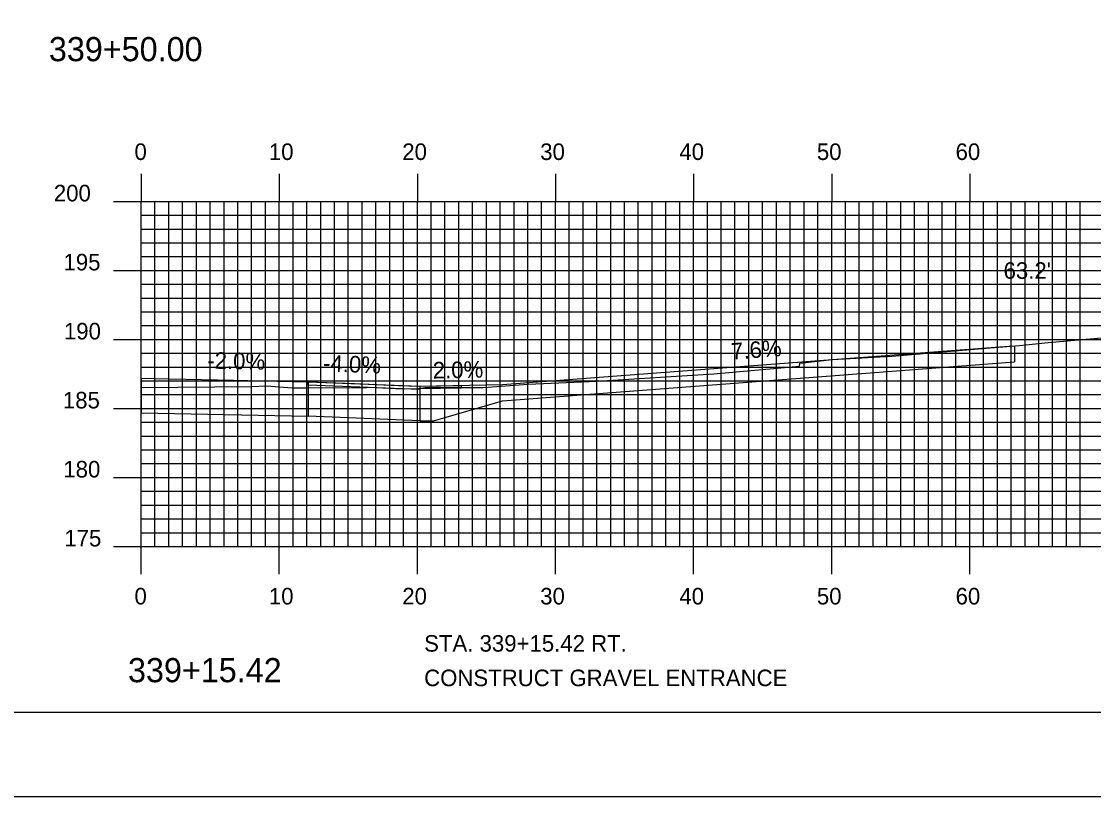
# Model space of a CAD drawing. Extents: x 1824360 to 1824703, y 442591 to 442811.
# Drawn here: x 1824516.7 to 1824594.3, y 442590.5 to 442646.7 of the extents above; entities that cross this region are included whole.
import ezdxf

# ---------------------------------------------------------------- set-up
doc = ezdxf.new("R2010")
doc.units = 0
for name, color, linetype in [('ANNOTATION', 7, 'Continuous'), ('BORDER', 7, 'Continuous'), ('D_Roadway_Centerline', 7, 'Continuous'), ('D_Roadway_Edge_Shoulder', 7, 'Continuous'), ('D_Roadway_FinishedGrade', 7, 'Continuous'), ('D_Text_Standard', 7, 'Continuous'), ('H_V ANNOTATION', 7, 'Continuous'), ('MAJOR', 7, 'Continuous'), ('MINOR', 7, 'Continuous'), ('PLOT BOUNDARY', 7, 'Continuous'), ('S_Roadway_Centerline', 7, 'Continuous')]:
    doc.layers.add(name, color=color, linetype=linetype)

msp = doc.modelspace()

# ---------------------------------------------------------------- linework, layer by layer
at = {"layer": 'ANNOTATION'}
for points in [[(1824545.506, 442620.277), (1824548.506, 442620.337), (1824548.506, 442620.17)], [(1824545.506, 442620.277), (1824545.506, 442620.11), (1824548.506, 442620.17)]]:
    msp.add_lwpolyline(points, dxfattribs=at)
at = {"layer": 'BORDER'}
msp.add_lwpolyline([(1824375.735, 442596.665), (1824695.735, 442596.665), (1824695.735, 442806.665), (1824375.735, 442806.665)], close=True, dxfattribs=at)
at = {"layer": 'D_Roadway_Centerline'}
msp.add_lwpolyline([(1824525.335, 442620.85), (1824525.335, 442620.85), (1824527.319, 442620.809), (1824528.58, 442620.783), (1824532.021, 442620.713), (1824536.27, 442620.626), (1824536.724, 442620.617), (1824537.438, 442620.602), (1824540.777, 442620.467), (1824543.959, 442620.339), (1824544.714, 442620.309), (1824545.506, 442620.277)], dxfattribs=at)
at = {"layer": 'D_Roadway_Edge_Shoulder'}
msp.add_lwpolyline([(1824537.438, 442620.602), (1824545.506, 442620.277), (1824545.506, 442620.027), (1824537.438, 442620.352)], close=True, dxfattribs=at)
msp.add_lwpolyline([(1824537.438, 442620.602), (1824545.506, 442620.277), (1824545.506, 442620.027), (1824537.438, 442620.352)], close=True, dxfattribs=at)
at = {"layer": 'D_Roadway_FinishedGrade'}
for p, q in [((1824588.582, 442623.208), (1824588.582, 442622.048)), ((1824537.438, 442620.602), (1824537.438, 442618.102)), ((1824545.506, 442620.277), (1824551.506, 442620.397)), ((1824546.506, 442617.777), (1824551.506, 442619.227)), ((1824545.506, 442617.777), (1824546.506, 442617.777))]:
    msp.add_line(p, q, dxfattribs=at)
for points in [[(1824551.506, 442620.397), (1824587.506, 442623.133), (1824588.582, 442623.208)], [(1824551.506, 442619.227), (1824588.582, 442622.044)], [(1824525.335, 442620.85), (1824525.335, 442618.35), (1824537.438, 442618.102)], [(1824545.506, 442620.277), (1824545.506, 442617.777), (1824537.438, 442618.102)]]:
    msp.add_lwpolyline(points, dxfattribs=at)
at = {"layer": 'MAJOR'}
for p, q in [((1824525.335, 442635.669), (1824525.335, 442633.665)), ((1824535.335, 442635.669), (1824535.335, 442633.665)), ((1824545.335, 442635.669), (1824545.335, 442633.665)), ((1824555.335, 442635.669), (1824555.335, 442633.665)), ((1824565.335, 442635.669), (1824565.335, 442633.665)), ((1824575.335, 442635.669), (1824575.335, 442633.665)), ((1824585.335, 442635.669), (1824585.335, 442633.665)), ((1824523.331, 442633.665), (1824525.335, 442633.665)), ((1824525.335, 442633.665), (1824665.335, 442633.665)), ((1824525.335, 442608.665), (1824525.335, 442633.665)), ((1824525.335, 442608.665), (1824525.335, 442633.665)), ((1824525.335, 442633.665), (1824665.335, 442633.665)), ((1824535.335, 442608.665), (1824535.335, 442633.665)), ((1824545.335, 442608.665), (1824545.335, 442633.665)), ((1824555.335, 442608.665), (1824555.335, 442633.665)), ((1824565.335, 442608.665), (1824565.335, 442633.665)), ((1824575.335, 442608.665), (1824575.335, 442633.665)), ((1824585.335, 442608.665), (1824585.335, 442633.665)), ((1824523.331, 442628.665), (1824525.335, 442628.665)), ((1824525.335, 442628.665), (1824665.335, 442628.665)), ((1824523.331, 442623.665), (1824525.335, 442623.665)), ((1824525.335, 442623.665), (1824665.335, 442623.665)), ((1824523.331, 442618.665), (1824525.335, 442618.665)), ((1824525.335, 442618.665), (1824665.335, 442618.665)), ((1824523.331, 442613.665), (1824525.335, 442613.665)), ((1824525.335, 442613.665), (1824665.335, 442613.665)), ((1824523.331, 442608.665), (1824525.335, 442608.665)), ((1824525.335, 442608.665), (1824665.335, 442608.665)), ((1824525.335, 442608.665), (1824665.335, 442608.665)), ((1824525.335, 442606.661), (1824525.335, 442608.665)), ((1824535.335, 442606.661), (1824535.335, 442608.665)), ((1824545.335, 442606.661), (1824545.335, 442608.665)), ((1824555.335, 442606.661), (1824555.335, 442608.665)), ((1824565.335, 442606.661), (1824565.335, 442608.665)), ((1824575.335, 442606.661), (1824575.335, 442608.665)), ((1824585.335, 442606.661), (1824585.335, 442608.665))]:
    msp.add_line(p, q, dxfattribs=at)
at = {"layer": 'MINOR'}
for p, q in [((1824526.335, 442608.665), (1824526.335, 442633.665)), ((1824527.335, 442608.665), (1824527.335, 442633.665)), ((1824528.335, 442608.665), (1824528.335, 442633.665)), ((1824529.335, 442608.665), (1824529.335, 442633.665)), ((1824530.335, 442608.665), (1824530.335, 442633.665)), ((1824531.335, 442608.665), (1824531.335, 442633.665)), ((1824532.335, 442608.665), (1824532.335, 442633.665)), ((1824533.335, 442608.665), (1824533.335, 442633.665)), ((1824534.335, 442608.665), (1824534.335, 442633.665)), ((1824536.335, 442608.665), (1824536.335, 442633.665)), ((1824537.335, 442608.665), (1824537.335, 442633.665)), ((1824538.335, 442608.665), (1824538.335, 442633.665)), ((1824539.335, 442608.665), (1824539.335, 442633.665)), ((1824540.335, 442608.665), (1824540.335, 442633.665)), ((1824541.335, 442608.665), (1824541.335, 442633.665)), ((1824542.335, 442608.665), (1824542.335, 442633.665)), ((1824543.335, 442608.665), (1824543.335, 442633.665)), ((1824544.335, 442608.665), (1824544.335, 442633.665)), ((1824546.335, 442608.665), (1824546.335, 442633.665)), ((1824547.335, 442608.665), (1824547.335, 442633.665)), ((1824548.335, 442608.665), (1824548.335, 442633.665)), ((1824549.335, 442608.665), (1824549.335, 442633.665)), ((1824550.335, 442608.665), (1824550.335, 442633.665)), ((1824551.335, 442608.665), (1824551.335, 442633.665)), ((1824552.335, 442608.665), (1824552.335, 442633.665)), ((1824553.335, 442608.665), (1824553.335, 442633.665)), ((1824554.335, 442608.665), (1824554.335, 442633.665)), ((1824556.335, 442608.665), (1824556.335, 442633.665)), ((1824557.335, 442608.665), (1824557.335, 442633.665)), ((1824558.335, 442608.665), (1824558.335, 442633.665)), ((1824559.335, 442608.665), (1824559.335, 442633.665)), ((1824560.335, 442608.665), (1824560.335, 442633.665)), ((1824561.335, 442608.665), (1824561.335, 442633.665)), ((1824562.335, 442608.665), (1824562.335, 442633.665)), ((1824563.335, 442608.665), (1824563.335, 442633.665)), ((1824564.335, 442608.665), (1824564.335, 442633.665)), ((1824566.335, 442608.665), (1824566.335, 442633.665)), ((1824567.335, 442608.665), (1824567.335, 442633.665)), ((1824568.335, 442608.665), (1824568.335, 442633.665)), ((1824569.335, 442608.665), (1824569.335, 442633.665)), ((1824570.335, 442608.665), (1824570.335, 442633.665)), ((1824571.335, 442608.665), (1824571.335, 442633.665)), ((1824572.335, 442608.665), (1824572.335, 442633.665)), ((1824573.335, 442608.665), (1824573.335, 442633.665)), ((1824574.335, 442608.665), (1824574.335, 442633.665)), ((1824576.335, 442608.665), (1824576.335, 442633.665)), ((1824577.335, 442608.665), (1824577.335, 442633.665)), ((1824578.335, 442608.665), (1824578.335, 442633.665)), ((1824579.335, 442608.665), (1824579.335, 442633.665)), ((1824580.335, 442608.665), (1824580.335, 442633.665)), ((1824581.335, 442608.665), (1824581.335, 442633.665)), ((1824582.335, 442608.665), (1824582.335, 442633.665)), ((1824583.335, 442608.665), (1824583.335, 442633.665)), ((1824584.335, 442608.665), (1824584.335, 442633.665)), ((1824586.335, 442608.665), (1824586.335, 442633.665)), ((1824587.335, 442608.665), (1824587.335, 442633.665)), ((1824588.335, 442608.665), (1824588.335, 442633.665)), ((1824589.335, 442608.665), (1824589.335, 442633.665)), ((1824590.335, 442608.665), (1824590.335, 442633.665)), ((1824591.335, 442608.665), (1824591.335, 442633.665)), ((1824592.335, 442608.665), (1824592.335, 442633.665)), ((1824593.335, 442608.665), (1824593.335, 442633.665)), ((1824525.335, 442632.665), (1824665.335, 442632.665)), ((1824525.335, 442632.665), (1824527.339, 442632.665)), ((1824525.335, 442631.665), (1824665.335, 442631.665)), ((1824525.335, 442631.665), (1824527.339, 442631.665)), ((1824525.335, 442630.665), (1824665.335, 442630.665)), ((1824525.335, 442630.665), (1824527.339, 442630.665)), ((1824525.335, 442629.665), (1824665.335, 442629.665)), ((1824525.335, 442629.665), (1824527.339, 442629.665)), ((1824525.335, 442627.665), (1824665.335, 442627.665)), ((1824525.335, 442627.665), (1824527.339, 442627.665)), ((1824525.335, 442626.665), (1824665.335, 442626.665)), ((1824525.335, 442626.665), (1824527.339, 442626.665)), ((1824525.335, 442625.665), (1824665.335, 442625.665)), ((1824525.335, 442625.665), (1824527.339, 442625.665)), ((1824525.335, 442624.665), (1824665.335, 442624.665)), ((1824525.335, 442624.665), (1824527.339, 442624.665)), ((1824525.335, 442622.665), (1824665.335, 442622.665)), ((1824525.335, 442622.665), (1824527.339, 442622.665)), ((1824525.335, 442621.665), (1824665.335, 442621.665)), ((1824525.335, 442621.665), (1824527.339, 442621.665)), ((1824525.335, 442620.665), (1824665.335, 442620.665)), ((1824525.335, 442620.665), (1824527.339, 442620.665)), ((1824525.335, 442619.665), (1824665.335, 442619.665)), ((1824525.335, 442619.665), (1824527.339, 442619.665)), ((1824525.335, 442617.665), (1824665.335, 442617.665)), ((1824525.335, 442617.665), (1824527.339, 442617.665)), ((1824525.335, 442616.665), (1824665.335, 442616.665)), ((1824525.335, 442616.665), (1824527.339, 442616.665)), ((1824525.335, 442615.665), (1824665.335, 442615.665)), ((1824525.335, 442615.665), (1824527.339, 442615.665)), ((1824525.335, 442614.665), (1824665.335, 442614.665)), ((1824525.335, 442614.665), (1824527.339, 442614.665)), ((1824525.335, 442612.665), (1824665.335, 442612.665)), ((1824525.335, 442612.665), (1824527.339, 442612.665)), ((1824525.335, 442611.665), (1824665.335, 442611.665)), ((1824525.335, 442611.665), (1824527.339, 442611.665)), ((1824525.335, 442610.665), (1824665.335, 442610.665)), ((1824525.335, 442610.665), (1824527.339, 442610.665)), ((1824525.335, 442609.665), (1824665.335, 442609.665)), ((1824525.335, 442609.665), (1824527.339, 442609.665))]:
    msp.add_line(p, q, dxfattribs=at)
at = {"layer": 'PLOT BOUNDARY'}
msp.add_lwpolyline([(1824359.548, 442590.547), (1824699.548, 442590.547), (1824699.548, 442810.547), (1824359.548, 442810.547)], close=True, dxfattribs=at)
at = {"layer": 'S_Roadway_Centerline'}
msp.add_lwpolyline([(1824525.335, 442620.189), (1824533.332, 442620.247), (1824534.422, 442620.304), (1824536.275, 442620.164), (1824537.228, 442620.15), (1824541.677, 442620.185), (1824541.861, 442620.209), (1824543.787, 442620.112), (1824545.262, 442620.077), (1824545.543, 442620.133), (1824545.889, 442620.173), (1824546.743, 442620.2), (1824547.93, 442620.172), (1824550.106, 442620.186), (1824553.358, 442620.419), (1824558.338, 442620.645), (1824566.796, 442621.165), (1824573.014, 442621.729), (1824573.033, 442621.942), (1824575.375, 442622.205), (1824579.701, 442622.448), (1824586.516, 442623.037), (1824588.928, 442623.236), (1824591.003, 442623.45), (1824595.698, 442623.844)], dxfattribs=at)

# ---------------------------------------------------------------- texts
at = {"layer": 'ANNOTATION'}
for s, rotation, p in [('7.6%', 4.33577, (1824568.093, 442622.19)), ('-2.0%', 358.82672, (1824530.112, 442621.552)), ('-4.0%', 357.69163, (1824538.491, 442621.361)), ('2.0%', 1.14576, (1824546.462, 442620.83))]:
    msp.add_text(s, height=1.2, rotation=rotation, dxfattribs=at).set_placement(p)
at = {"layer": 'D_Text_Standard'}
for s, p in [("63.2'", (1824587.782, 442628.056)), ('STA. 339+15.42 RT.', (1824545.828, 442601.046)), ('CONSTRUCT GRAVEL ENTRANCE', (1824545.828, 442598.546))]:
    msp.add_text(s, height=1.2, dxfattribs=at).set_placement(p)
at = {"layer": 'H_V ANNOTATION'}
for s, height, p in [('339+50.00', 1.75, (1824518.655, 442643.821)), ('0', 1.2, (1824524.853, 442636.665)), ('10', 1.2, (1824534.586, 442636.665)), ('20', 1.2, (1824544.243, 442636.665)), ('30', 1.2, (1824554.232, 442636.665)), ('40', 1.2, (1824564.307, 442636.665)), ('50', 1.2, (1824574.264, 442636.665)), ('60', 1.2, (1824584.307, 442636.665)), ('200', 1.2, (1824519.016, 442633.665)), ('195', 1.2, (1824519.713, 442628.665)), ('190', 1.2, (1824519.745, 442623.665)), ('185', 1.2, (1824519.67, 442618.665)), ('180', 1.2, (1824519.702, 442613.665)), ('175', 1.2, (1824519.776, 442608.665)), ('0', 1.2, (1824524.853, 442604.465)), ('10', 1.2, (1824534.586, 442604.465)), ('20', 1.2, (1824544.243, 442604.465)), ('30', 1.2, (1824554.232, 442604.465)), ('40', 1.2, (1824564.307, 442604.465)), ('50', 1.2, (1824574.264, 442604.465)), ('60', 1.2, (1824584.307, 442604.465)), ('339+15.42 ', 1.75, (1824524.383, 442598.831))]:
    msp.add_text(s, height=height, dxfattribs=at).set_placement(p)
at = {"layer": 'MAJOR'}
msp.add_text('-', height=0.012, dxfattribs=at).set_placement((1824525.326, 442608.665))

doc.saveas('drawing.dxf')
